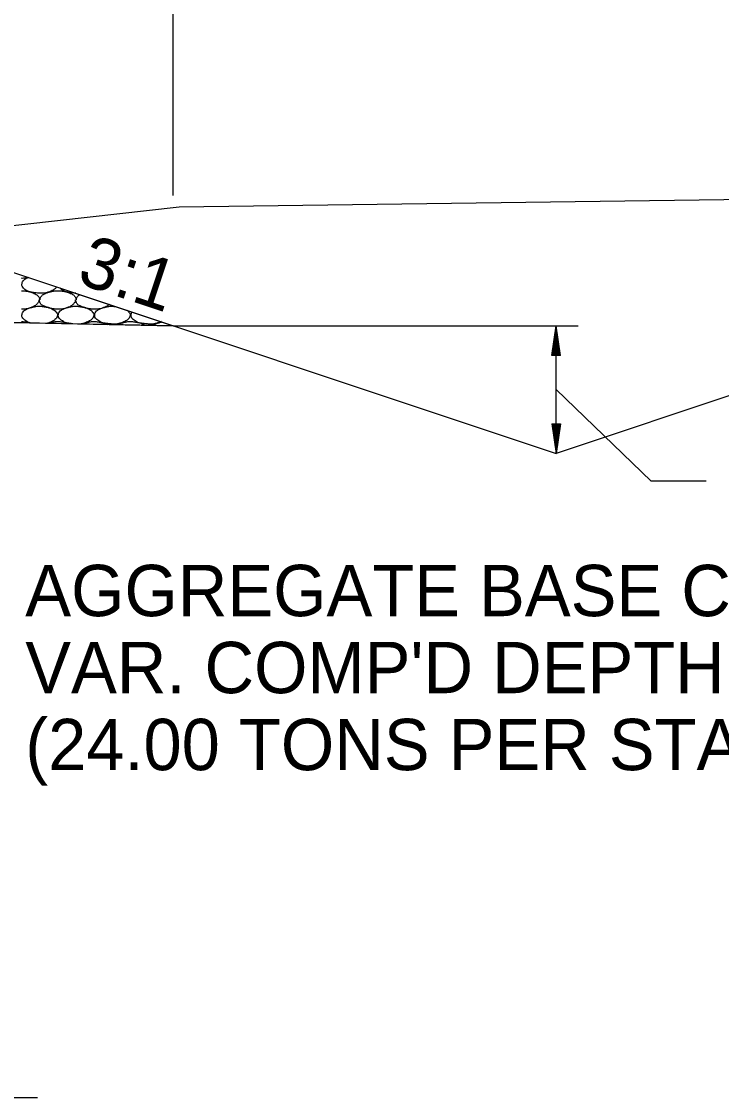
# Model space of a CAD drawing. Extents: x 1373719 to 1374161, y 379835 to 380167.
# Drawn here: x 1373990.08 to 1373998.95, y 379964.01 to 379977.64 of the extents above; entities that cross this region are included whole.
import ezdxf

# ---------------------------------------------------------------- set-up
doc = ezdxf.new("R2010")
doc.units = 0
for name, color, linetype in [('Agg Base Course Text', 7, 'Continuous'), ('Aggregate Base Course', 7, 'Continuous'), ('GREEN_TXT', 7, 'Continuous'), ('SIGNATURE', 7, 'Continuous'), ('T_Drafting', 7, 'Continuous')]:
    doc.layers.add(name, color=color, linetype=linetype)

msp = doc.modelspace()

# ---------------------------------------------------------------- linework, layer by layer
for p, q in [((1373984.855, 379976.169), (1373996.855, 379972.169)), ((1374006.816, 379975.489), (1373996.855, 379972.169)), ((1373965.355, 379974.318), (1373992.005, 379973.785))]:
    msp.add_line(p, q)
at = {"layer": 'Aggregate Base Course'}
for points, degree in [([(1373990.174, 379974.396), (1373990.155, 379974.39), (1373990.137, 379974.386), (1373990.106, 379974.385), (1373990.095, 379974.385), (1373990.083, 379974.386)], 3), ([(1373990.527, 379974.278), (1373990.523, 379974.272), (1373990.519, 379974.265), (1373990.505, 379974.25), (1373990.497, 379974.244), (1373990.468, 379974.228), (1373990.451, 379974.219), (1373990.405, 379974.205), (1373990.38, 379974.198), (1373990.34, 379974.196), (1373990.327, 379974.196), (1373990.294, 379974.198), (1373990.274, 379974.2), (1373990.233, 379974.204), (1373990.211, 379974.208), (1373990.172, 379974.217), (1373990.157, 379974.226), (1373990.123, 379974.247), (1373990.109, 379974.258), (1373990.09, 379974.288), (1373990.088, 379974.298), (1373990.09, 379974.323), (1373990.093, 379974.338), (1373990.114, 379974.366), (1373990.125, 379974.373), (1373990.15, 379974.386), (1373990.161, 379974.392), (1373990.173, 379974.396)], 3), ([(1373990.083, 379974.227), (1373990.085, 379974.227), (1373990.087, 379974.227), (1373990.089, 379974.227)], 2), ([(1373990.089, 379974.227), (1373990.115, 379974.228), (1373990.142, 379974.224), (1373990.168, 379974.218), (1373990.2, 379974.212), (1373990.23, 379974.202), (1373990.26, 379974.186), (1373990.28, 379974.175), (1373990.296, 379974.161), (1373990.307, 379974.141), (1373990.311, 379974.132), (1373990.313, 379974.123), (1373990.314, 379974.114), (1373990.314, 379974.113), (1373990.314, 379974.113), (1373990.314, 379974.112)], 3), ([(1373990.319, 379974.112), (1373990.319, 379974.113), (1373990.319, 379974.113), (1373990.319, 379974.114), (1373990.32, 379974.129), (1373990.324, 379974.144), (1373990.334, 379974.157), (1373990.344, 379974.171), (1373990.356, 379974.179), (1373990.37, 379974.186), (1373990.381, 379974.192), (1373990.393, 379974.198), (1373990.406, 379974.202), (1373990.424, 379974.208), (1373990.441, 379974.214), (1373990.46, 379974.218), (1373990.471, 379974.221), (1373990.482, 379974.224), (1373990.494, 379974.225), (1373990.51, 379974.228), (1373990.528, 379974.229), (1373990.544, 379974.227)], 3), ([(1373990.544, 379974.227), (1373990.546, 379974.227), (1373990.548, 379974.227), (1373990.55, 379974.227)], 2), ([(1373990.55, 379974.227), (1373990.576, 379974.228), (1373990.602, 379974.224), (1373990.629, 379974.218), (1373990.661, 379974.212), (1373990.691, 379974.202), (1373990.721, 379974.186), (1373990.741, 379974.175), (1373990.756, 379974.161), (1373990.767, 379974.141), (1373990.772, 379974.132), (1373990.774, 379974.123), (1373990.775, 379974.114), (1373990.775, 379974.113), (1373990.775, 379974.113), (1373990.775, 379974.112)], 3), ([(1373990.77, 379974.197), (1373990.751, 379974.198), (1373990.733, 379974.2), (1373990.693, 379974.204), (1373990.672, 379974.208), (1373990.633, 379974.217), (1373990.618, 379974.226), (1373990.588, 379974.245), (1373990.577, 379974.253), (1373990.567, 379974.265)], 3), ([(1373990.78, 379974.112), (1373990.78, 379974.113), (1373990.78, 379974.113), (1373990.78, 379974.129), (1373990.785, 379974.144), (1373990.802, 379974.167), (1373990.811, 379974.174), (1373990.82, 379974.18)], 3), ([(1373990.303, 379974.112), (1373990.303, 379974.11), (1373990.303, 379974.108), (1373990.303, 379974.107), (1373990.302, 379974.088), (1373990.291, 379974.073), (1373990.278, 379974.058), (1373990.27, 379974.049), (1373990.261, 379974.042), (1373990.251, 379974.036), (1373990.233, 379974.026), (1373990.215, 379974.018), (1373990.195, 379974.011), (1373990.169, 379974.003), (1373990.144, 379973.996), (1373990.118, 379973.995), (1373990.106, 379973.995), (1373990.095, 379973.995), (1373990.083, 379973.995)], 3), ([(1373990.544, 379973.995), (1373990.542, 379973.995), (1373990.539, 379973.995), (1373990.537, 379973.995), (1373990.517, 379973.995), (1373990.497, 379973.997), (1373990.478, 379974), (1373990.457, 379974.004), (1373990.437, 379974.011), (1373990.416, 379974.017), (1373990.398, 379974.022), (1373990.381, 379974.027), (1373990.364, 379974.035), (1373990.345, 379974.043), (1373990.329, 379974.057), (1373990.319, 379974.076), (1373990.314, 379974.086), (1373990.312, 379974.096), (1373990.312, 379974.107), (1373990.312, 379974.108), (1373990.312, 379974.11), (1373990.312, 379974.112)], 3), ([(1373990.764, 379974.112), (1373990.764, 379974.11), (1373990.764, 379974.108), (1373990.764, 379974.107), (1373990.763, 379974.088), (1373990.752, 379974.073), (1373990.739, 379974.058), (1373990.73, 379974.049), (1373990.722, 379974.042), (1373990.712, 379974.036), (1373990.693, 379974.026), (1373990.676, 379974.018), (1373990.656, 379974.011), (1373990.63, 379974.003), (1373990.605, 379973.996), (1373990.578, 379973.995), (1373990.567, 379973.995), (1373990.556, 379973.995), (1373990.544, 379973.995)], 3), ([(1373991.005, 379973.995), (1373991.003, 379973.995), (1373991, 379973.995), (1373990.998, 379973.995), (1373990.978, 379973.995), (1373990.958, 379973.997), (1373990.938, 379974), (1373990.917, 379974.004), (1373990.897, 379974.011), (1373990.877, 379974.017), (1373990.859, 379974.022), (1373990.842, 379974.027), (1373990.825, 379974.035), (1373990.806, 379974.043), (1373990.79, 379974.057), (1373990.78, 379974.076), (1373990.775, 379974.086), (1373990.773, 379974.096), (1373990.773, 379974.107), (1373990.773, 379974.108), (1373990.773, 379974.11), (1373990.773, 379974.112)], 3), ([(1373991.196, 379974.055), (1373991.189, 379974.047), (1373991.181, 379974.042), (1373991.154, 379974.026), (1373991.136, 379974.018), (1373991.091, 379974.003), (1373991.066, 379973.996), (1373991.028, 379973.995), (1373991.016, 379973.995), (1373991.005, 379973.995)], 3), ([(1373990.193, 379973.822), (1373990.192, 379973.822), (1373990.191, 379973.822), (1373990.172, 379973.826), (1373990.157, 379973.836), (1373990.123, 379973.857), (1373990.109, 379973.868), (1373990.09, 379973.897), (1373990.088, 379973.908), (1373990.09, 379973.932), (1373990.093, 379973.947), (1373990.114, 379973.975), (1373990.125, 379973.982), (1373990.151, 379973.996), (1373990.163, 379974.002), (1373990.193, 379974.012), (1373990.211, 379974.017), (1373990.241, 379974.025), (1373990.252, 379974.027), (1373990.28, 379974.032), (1373990.297, 379974.033), (1373990.314, 379974.031)], 3), ([(1373990.314, 379974.031), (1373990.34, 379974.031), (1373990.367, 379974.027), (1373990.425, 379974.015), (1373990.455, 379974.006), (1373990.505, 379973.979), (1373990.518, 379973.965), (1373990.537, 379973.936), (1373990.54, 379973.926), (1373990.536, 379973.901), (1373990.527, 379973.884), (1373990.505, 379973.86), (1373990.497, 379973.853), (1373990.468, 379973.837), (1373990.451, 379973.829), (1373990.425, 379973.82), (1373990.419, 379973.819), (1373990.414, 379973.817)], 3), ([(1373990.72, 379973.811), (1373990.718, 379973.811), (1373990.717, 379973.811), (1373990.693, 379973.814), (1373990.672, 379973.817), (1373990.633, 379973.826), (1373990.618, 379973.836), (1373990.584, 379973.857), (1373990.569, 379973.868), (1373990.55, 379973.897), (1373990.549, 379973.908), (1373990.55, 379973.932), (1373990.554, 379973.947), (1373990.575, 379973.975), (1373990.586, 379973.982), (1373990.612, 379973.996), (1373990.623, 379974.002), (1373990.654, 379974.012), (1373990.672, 379974.017), (1373990.701, 379974.025), (1373990.713, 379974.027), (1373990.741, 379974.032), (1373990.758, 379974.033), (1373990.775, 379974.031)], 3), ([(1373990.775, 379974.031), (1373990.801, 379974.031), (1373990.827, 379974.027), (1373990.886, 379974.015), (1373990.916, 379974.006), (1373990.966, 379973.979), (1373990.979, 379973.965), (1373990.998, 379973.936), (1373991.001, 379973.926), (1373990.997, 379973.901), (1373990.988, 379973.884), (1373990.966, 379973.86), (1373990.958, 379973.853), (1373990.929, 379973.837), (1373990.911, 379973.829), (1373990.873, 379973.817), (1373990.855, 379973.812), (1373990.837, 379973.809)], 3), ([(1373991.422, 379973.98), (1373991.434, 379973.97), (1373991.444, 379973.959), (1373991.459, 379973.936), (1373991.462, 379973.926), (1373991.457, 379973.901), (1373991.449, 379973.884), (1373991.427, 379973.86), (1373991.418, 379973.853), (1373991.39, 379973.837), (1373991.372, 379973.829), (1373991.327, 379973.814), (1373991.301, 379973.808), (1373991.262, 379973.805), (1373991.249, 379973.805), (1373991.216, 379973.807), (1373991.196, 379973.809), (1373991.154, 379973.814), (1373991.133, 379973.817), (1373991.094, 379973.826), (1373991.078, 379973.836), (1373991.045, 379973.857), (1373991.03, 379973.868), (1373991.011, 379973.897), (1373991.01, 379973.908), (1373991.011, 379973.932), (1373991.014, 379973.947), (1373991.035, 379973.975), (1373991.047, 379973.982), (1373991.073, 379973.996), (1373991.084, 379974.002), (1373991.115, 379974.012), (1373991.133, 379974.017), (1373991.162, 379974.025), (1373991.173, 379974.027), (1373991.202, 379974.032), (1373991.219, 379974.033), (1373991.235, 379974.031)], 3), ([(1373991.235, 379974.031), (1373991.248, 379974.031), (1373991.261, 379974.03), (1373991.274, 379974.029)], 2), ([(1373991.85, 379973.837), (1373991.838, 379973.831), (1373991.826, 379973.826), (1373991.788, 379973.814), (1373991.762, 379973.808), (1373991.723, 379973.805), (1373991.709, 379973.805), (1373991.676, 379973.807), (1373991.657, 379973.809), (1373991.615, 379973.814), (1373991.594, 379973.817), (1373991.554, 379973.826), (1373991.539, 379973.836), (1373991.506, 379973.857), (1373991.491, 379973.868), (1373991.472, 379973.897), (1373991.471, 379973.908), (1373991.472, 379973.932), (1373991.475, 379973.946), (1373991.484, 379973.959)], 3), ([(1373990.083, 379973.837), (1373990.085, 379973.837), (1373990.087, 379973.837), (1373990.089, 379973.837)], 2), ([(1373990.089, 379973.837), (1373990.115, 379973.837), (1373990.142, 379973.833), (1373990.177, 379973.826), (1373990.185, 379973.824), (1373990.194, 379973.822)], 3), ([(1373990.422, 379973.817), (1373990.435, 379973.821), (1373990.447, 379973.824), (1373990.471, 379973.831), (1373990.482, 379973.833), (1373990.51, 379973.837), (1373990.528, 379973.838), (1373990.544, 379973.837)], 3), ([(1373990.544, 379973.837), (1373990.546, 379973.837), (1373990.548, 379973.837), (1373990.55, 379973.837)], 2), ([(1373990.55, 379973.837), (1373990.576, 379973.837), (1373990.602, 379973.833), (1373990.648, 379973.824), (1373990.667, 379973.819), (1373990.685, 379973.812)], 3), ([(1373990.858, 379973.808), (1373990.861, 379973.809), (1373990.863, 379973.81), (1373990.884, 379973.818), (1373990.902, 379973.823), (1373990.932, 379973.831), (1373990.943, 379973.833), (1373990.971, 379973.837), (1373990.988, 379973.838), (1373991.005, 379973.837)], 3), ([(1373991.005, 379973.837), (1373991.007, 379973.837), (1373991.009, 379973.837), (1373991.01, 379973.837)], 2), ([(1373991.01, 379973.837), (1373991.037, 379973.837), (1373991.063, 379973.833), (1373991.117, 379973.822), (1373991.143, 379973.814), (1373991.168, 379973.802)], 3), ([(1373991.299, 379973.799), (1373991.308, 379973.804), (1373991.318, 379973.808), (1373991.345, 379973.818), (1373991.363, 379973.823), (1373991.393, 379973.831), (1373991.404, 379973.833), (1373991.432, 379973.837), (1373991.449, 379973.838), (1373991.466, 379973.837)], 3), ([(1373991.466, 379973.837), (1373991.468, 379973.837), (1373991.469, 379973.837), (1373991.471, 379973.837)], 2), ([(1373991.471, 379973.837), (1373991.498, 379973.837), (1373991.524, 379973.833), (1373991.583, 379973.821), (1373991.612, 379973.811), (1373991.644, 379973.794), (1373991.646, 379973.793), (1373991.647, 379973.792)], 3), ([(1373991.743, 379973.791), (1373991.746, 379973.792), (1373991.749, 379973.794), (1373991.764, 379973.801), (1373991.775, 379973.807), (1373991.806, 379973.818), (1373991.824, 379973.823), (1373991.849, 379973.829), (1373991.856, 379973.831), (1373991.863, 379973.833)], 3)]:
    msp.add_open_spline(points, degree=degree, dxfattribs=at)
at = {"layer": 'GREEN_TXT'}
for p, q in [((1373992.005, 379975.434), (1373992.005, 379989.371)), ((1373992.005, 379973.785), (1373997.132, 379973.785)), ((1373996.799, 379973.41), (1373996.855, 379973.785)), ((1373996.855, 379972.169), (1373996.855, 379973.785)), ((1373996.911, 379973.41), (1373996.855, 379973.785)), ((1373996.808, 379973.41), (1373996.855, 379973.723)), ((1373996.817, 379973.41), (1373996.855, 379973.658)), ((1373996.902, 379973.41), (1373996.855, 379973.723)), ((1373996.892, 379973.41), (1373996.855, 379973.658)), ((1373996.827, 379973.41), (1373996.855, 379973.596)), ((1373996.836, 379973.41), (1373996.855, 379973.532)), ((1373996.883, 379973.41), (1373996.855, 379973.596)), ((1373996.873, 379973.41), (1373996.855, 379973.532)), ((1373996.911, 379973.41), (1373996.799, 379973.41)), ((1373996.846, 379973.41), (1373996.855, 379973.47)), ((1373996.864, 379973.41), (1373996.855, 379973.47)), ((1373996.799, 379972.544), (1373996.855, 379972.169)), ((1373996.799, 379972.544), (1373996.911, 379972.544)), ((1373996.808, 379972.544), (1373996.855, 379972.231)), ((1373996.817, 379972.544), (1373996.855, 379972.296)), ((1373996.827, 379972.544), (1373996.855, 379972.358)), ((1373996.837, 379972.544), (1373996.855, 379972.422)), ((1373996.846, 379972.544), (1373996.855, 379972.484)), ((1373996.911, 379972.544), (1373996.855, 379972.169)), ((1373996.873, 379972.544), (1373996.855, 379972.422)), ((1373996.892, 379972.544), (1373996.855, 379972.296)), ((1373996.902, 379972.544), (1373996.855, 379972.231)), ((1373996.883, 379972.544), (1373996.855, 379972.358)), ((1373996.864, 379972.544), (1373996.855, 379972.484)), ((1373941.741, 379964.012), (1373990.285, 379964.012))]:
    msp.add_line(p, q, dxfattribs=at)
msp.add_lwpolyline([(1373998.754, 379971.817), (1373998.058, 379971.817), (1373996.855, 379972.977)], dxfattribs=at)
at = {"layer": 'SIGNATURE'}
msp.add_lwpolyline([(1373983.955, 379975.834), (1373984.855, 379975.798), (1373984.469, 379976.184), (1373984.855, 379976.169), (1373987.02, 379975.447), (1373992.005, 379973.785), (1373983.114, 379973.963), (1373983.955, 379975.834)], dxfattribs=at)
at = {"layer": 'T_Drafting'}
msp.add_lwpolyline([(1373907.347, 379968.924), (1373923.894, 379968.848), (1373942.81, 379971.015), (1373964.304, 379972.17), (1373992.078, 379975.291), (1374006.816, 379975.489), (1374019.984, 379975.489)], dxfattribs=at)

# ---------------------------------------------------------------- texts
at = {"layer": 'Agg Base Course Text'}
for s, p in [('AGGREGATE BASE CRSE. (CL. 7)', (1373990.131, 379970.107)), ("VAR. COMP'D DEPTH", (1373990.131, 379969.132)), ('(24.00 TONS PER STA.)', (1373990.131, 379968.157))]:
    msp.add_text(s, height=0.65, dxfattribs=at).set_placement(p)
at = {"layer": 'GREEN_TXT'}
msp.add_text('3:1', height=0.65, rotation=341.5651, dxfattribs=at).set_placement((1373990.765, 379974.332))

doc.saveas('drawing.dxf')
